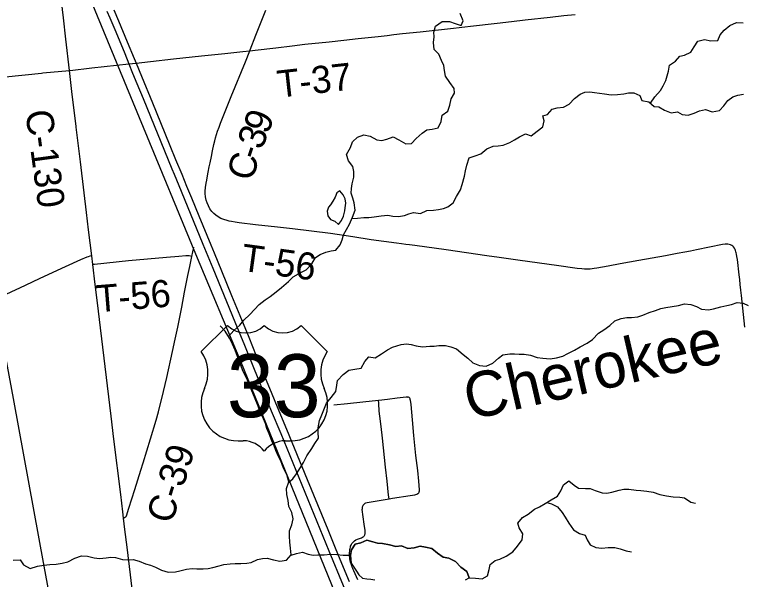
# Model space of a CAD drawing. Extents: x 0 to 34, y -5.4 to 22.
# Drawn here: x 6.179 to 7.705, y 15.309 to 16.492 of the extents above; entities that cross this region are included whole.
import ezdxf

# ---------------------------------------------------------------- set-up
doc = ezdxf.new("R2010")
doc.units = 0
for name, color, linetype in [('GM_X_County_Road', 7, 'Continuous'), ('GM_X_County_Road_Text', 7, 'Continuous'), ('GM_X_Minor_Lake', 7, 'Continuous'), ('GM_X_Minor_River', 7, 'Continuous'), ('GM_X_Minor_River_Text', 7, 'Continuous'), ('GM_X_Rail_Line', 7, 'Continuous'), ('GM_X_Township_Road', 7, 'Continuous'), ('GM_X_Township_Road_Text', 7, 'Continuous'), ('GM_X_US_Location', 7, 'Continuous'), ('GM_X_US_Route', 7, 'Continuous'), ('GM_X_US_Shield', 7, 'Continuous')]:
    doc.layers.add(name, color=color, linetype=linetype)

msp = doc.modelspace()

# ---------------------------------------------------------------- linework, layer by layer
at = {"layer": 'GM_X_County_Road'}
msp.add_line((6.3428, 15.9686), (6.3405, 15.9872), dxfattribs=at)
for points in [[(6.2815, 16.4857), (6.2776, 16.5205), (6.2729, 16.5674)], [(6.5919, 16.0798), (6.588, 16.0855), (6.5847, 16.0918), (6.5821, 16.0978), (6.58, 16.1037), (6.5787, 16.1105), (6.5782, 16.1172), (6.5783, 16.1221), (6.5788, 16.1301), (6.5801, 16.1392), (6.5813, 16.1453), (6.583, 16.1542), (6.5845, 16.1618), (6.5867, 16.173), (6.5884, 16.1816), (6.5912, 16.1953), (6.5935, 16.2065), (6.5964, 16.2202), (6.5982, 16.2276), (6.5999, 16.234), (6.6018, 16.2408), (6.604, 16.2477), (6.6072, 16.2564), (6.6101, 16.2646), (6.6183, 16.2854), (6.6327, 16.3204), (6.6622, 16.393), (6.6714, 16.4165), (6.6722, 16.4184), (6.6843, 16.4492), (6.6965, 16.4804), (6.7049, 16.5017)], [(6.3081, 16.2562), (6.3079, 16.2582), (6.2995, 16.3248), (6.2938, 16.3751), (6.2864, 16.4409), (6.2815, 16.4857)], [(6.4185, 16.3889), (6.4334, 16.3904), (6.4635, 16.3939), (6.5117, 16.3995), (6.5704, 16.4057), (6.6193, 16.4107), (6.657, 16.4148), (6.6714, 16.4165)], [(6.2351, 16.3696), (6.2381, 16.3699), (6.2938, 16.3751), (6.2957, 16.3753), (6.3407, 16.3804), (6.4185, 16.3889)], [(4.7185, 16.204), (4.7926, 16.2124), (4.8952, 16.2234), (5.0348, 16.2385), (5.0448, 16.2396), (5.088, 16.2444), (5.2441, 16.2625), (5.3244, 16.2711), (5.3683, 16.2761), (5.4411, 16.2844), (5.561, 16.2977), (5.6252, 16.3051), (5.6696, 16.3102), (5.688, 16.3123), (5.7221, 16.3161), (5.769, 16.3213), (5.8104, 16.3259), (5.8666, 16.332), (5.9123, 16.337), (6.0063, 16.3464), (6.1102, 16.3568), (6.1602, 16.3621), (6.2351, 16.3696)], [(6.3405, 15.9872), (6.3339, 16.0417), (6.3298, 16.0775), (6.3248, 16.1188), (6.3169, 16.1836), (6.3081, 16.2562)], [(6.4073, 15.4374), (6.4092, 15.4386), (6.4111, 15.44), (6.4125, 15.4412), (6.4132, 15.4423), (6.4186, 15.4584), (6.4309, 15.4975), (6.4434, 15.5378), (6.4482, 15.5532), (6.4637, 15.6037), (6.4753, 15.6424), (6.4802, 15.6603), (6.4907, 15.7025), (6.4978, 15.7321), (6.5098, 15.7867), (6.5151, 15.8122), (6.5205, 15.8378), (6.529, 15.8791), (6.5351, 15.9108), (6.5421, 15.9455), (6.5462, 15.9644), (6.5504, 15.9858), (6.5543, 16.0054)], [(6.4464, 15.1211), (6.4431, 15.144), (6.4342, 15.2168), (6.4265, 15.2778), (6.4217, 15.3185), (6.4147, 15.3765), (6.4102, 15.4135), (6.4073, 15.4374), (6.4056, 15.4505), (6.4013, 15.4867), (6.3872, 15.6026), (6.3811, 15.6513), (6.3588, 15.8364), (6.3525, 15.8882), (6.3478, 15.927), (6.3428, 15.9686)]]:
    msp.add_lwpolyline(points, dxfattribs=at)
at = {"layer": 'GM_X_Minor_Lake'}
for points in [[(6.8701, 16.0814), (6.8713, 16.0877), (6.8722, 16.0972), (6.8712, 16.1063), (6.8672, 16.1144), (6.8601, 16.1228), (6.854, 16.1188), (6.8505, 16.1097), (6.845, 16.1014), (6.8404, 16.0935)], [(6.8404, 16.0935), (6.8361, 16.0887), (6.8333, 16.0803), (6.8351, 16.0708), (6.8407, 16.0628), (6.8493, 16.0592), (6.8575, 16.0522), (6.8637, 16.0609), (6.8677, 16.0699), (6.8701, 16.0814)], [(7.1305, 15.3128), (7.1261, 15.3254), (7.1134, 15.3347), (7.1023, 15.3466), (7.088, 15.3537), (7.0763, 15.3558), (7.0647, 15.3643), (7.0528, 15.3736), (7.0396, 15.3765), (7.0279, 15.3786), (7.0157, 15.3754), (7.0021, 15.3737), (6.9893, 15.3793), (6.9772, 15.378), (6.9636, 15.3816), (6.9492, 15.3841), (6.9387, 15.3851), (6.9289, 15.3879), (6.9164, 15.3915), (6.9039, 15.386), (6.8917, 15.3832), (6.8847, 15.3712), (6.8823, 15.3598)], [(6.8823, 15.3598), (6.8829, 15.3514), (6.884, 15.343), (6.8891, 15.335), (6.8951, 15.3262), (6.8995, 15.3185), (6.9077, 15.3119), (6.9168, 15.3102), (6.9247, 15.3094), (6.9331, 15.3081)], [(7.1233, 15.3085), (7.1305, 15.3128)]]:
    msp.add_lwpolyline(points, dxfattribs=at)
at = {"layer": 'GM_X_Minor_River'}
for points in [[(6.627, 15.8176), (6.638, 15.8302), (6.6503, 15.8414), (6.6592, 15.8519), (6.6715, 15.8638), (6.6815, 15.8746), (6.6912, 15.8847), (6.7038, 15.8947), (6.7138, 15.9018), (6.7268, 15.9114), (6.7379, 15.9203), (6.7525, 15.933), (6.7625, 15.9427), (6.7786, 15.9519), (6.7896, 15.9574), (6.8016, 15.9701), (6.809, 15.9836), (6.8185, 15.9895), (6.8304, 15.9946), (6.8421, 15.9971), (6.8516, 15.9988), (6.8609, 16.0097), (6.8645, 16.0206), (6.8677, 16.0308), (6.8739, 16.0421), (6.8801, 16.053), (6.8868, 16.068), (6.892, 16.0824), (6.89, 16.0976), (6.8875, 16.1075), (6.8839, 16.1182), (6.8844, 16.1277), (6.8861, 16.1379), (6.8894, 16.1519), (6.8892, 16.1632), (6.8871, 16.1739), (6.8782, 16.1862), (6.8742, 16.1988), (6.8824, 16.2135), (6.8864, 16.2259), (6.8968, 16.2352), (6.9101, 16.2403), (6.9237, 16.2374), (6.9376, 16.23), (6.9478, 16.2287), (6.958, 16.2315), (6.9714, 16.2362), (6.9837, 16.2296), (6.998, 16.2217), (7.0101, 16.2223), (7.0197, 16.2324), (7.032, 16.2435), (7.0424, 16.2506), (7.053, 16.2523), (7.0659, 16.2551), (7.0722, 16.2683), (7.0743, 16.2815), (7.0861, 16.2897), (7.0901, 16.3025), (7.093, 16.3157), (7.1, 16.3278), (7.0994, 16.3373), (7.0902, 16.3499), (7.0809, 16.363), (7.0788, 16.3752), (7.0775, 16.3858), (7.0728, 16.3962), (7.0673, 16.4095), (7.0576, 16.4192), (7.0563, 16.4336), (7.0577, 16.4457), (7.0567, 16.4552), (7.0599, 16.4677), (7.0741, 16.4777), (7.0892, 16.4778), (7.1013, 16.4735), (7.1141, 16.4694), (7.1184, 16.4792), (7.1115, 16.4942)], [(7.5101, 16.3066), (7.5196, 16.3202), (7.5312, 16.3333), (7.5366, 16.3431), (7.5421, 16.3544), (7.5453, 16.3642), (7.5477, 16.374), (7.5502, 16.3861), (7.5624, 16.3946), (7.5717, 16.4051), (7.5816, 16.4072), (7.5949, 16.4134), (7.6015, 16.4247), (7.6093, 16.4363), (7.623, 16.4403), (7.6366, 16.437), (7.6513, 16.4379), (7.6564, 16.4499), (7.6645, 16.4597), (7.6764, 16.469), (7.6905, 16.4759), (7.7045, 16.4749)], [(6.8855, 16.065), (6.897, 16.066), (6.9103, 16.0669), (6.9205, 16.0675), (6.9319, 16.0688), (6.9467, 16.0704), (6.9603, 16.0721), (6.9709, 16.0697), (6.9826, 16.0691), (6.9951, 16.0711), (7.0046, 16.0751), (7.0145, 16.078), (7.0289, 16.0759), (7.0422, 16.0821), (7.0562, 16.0826), (7.0668, 16.0836), (7.0767, 16.0857), (7.0862, 16.0897), (7.0974, 16.0982), (7.1044, 16.111), (7.1126, 16.1253), (7.1158, 16.1362), (7.1206, 16.1536), (7.1227, 16.165), (7.1255, 16.1771), (7.1307, 16.1921), (7.1433, 16.1965), (7.1551, 16.2005), (7.1677, 16.2112), (7.1807, 16.2167), (7.1913, 16.2173), (7.2019, 16.2186), (7.2156, 16.2245), (7.2256, 16.23), (7.2359, 16.2359), (7.2488, 16.2421), (7.2605, 16.2381), (7.2728, 16.2478), (7.285, 16.2571), (7.2875, 16.2699), (7.2847, 16.2798), (7.2946, 16.2827), (7.3042, 16.2943), (7.3148, 16.2971), (7.3285, 16.2984), (7.3399, 16.3043), (7.3511, 16.3166), (7.363, 16.3255), (7.3725, 16.3299), (7.3835, 16.3305), (7.3933, 16.3288), (7.4137, 16.3262), (7.4277, 16.3241), (7.4413, 16.3246), (7.4542, 16.3259), (7.4645, 16.3284), (7.4754, 16.3282), (7.4882, 16.3226), (7.4922, 16.3123), (7.5065, 16.3098), (7.5181, 16.2994), (7.5279, 16.2988), (7.5399, 16.2922), (7.5535, 16.2866), (7.5667, 16.2883), (7.5765, 16.2832), (7.589, 16.2815), (7.6019, 16.2854), (7.6126, 16.2905), (7.6255, 16.2934), (7.6394, 16.2886), (7.655, 16.291), (7.6638, 16.301), (7.672, 16.3119), (7.6827, 16.3201), (7.693, 16.3237), (7.7051, 16.3258)], [(6.7526, 15.5119), (6.7615, 15.5197), (6.7693, 15.5306), (6.7774, 15.5433), (6.7837, 15.5542), (6.7911, 15.5681), (6.8012, 15.5831), (6.8078, 15.594), (6.8152, 15.6049), (6.8146, 15.6167), (6.8144, 15.6265), (6.8177, 15.642), (6.8221, 15.6541), (6.8264, 15.6643), (6.8319, 15.6782), (6.8416, 15.6902), (6.8516, 15.7029), (6.8534, 15.7162), (6.855, 15.726), (6.867, 15.7387), (6.8789, 15.7472), (6.8914, 15.7497), (6.9047, 15.7517), (6.9125, 15.7656), (6.921, 15.7757), (6.9342, 15.7736), (6.9475, 15.7813), (6.9594, 15.7902), (6.9701, 15.7957), (6.9884, 15.8011), (6.9994, 15.8025), (7.0092, 15.8011), (7.0197, 15.7987), (7.0329, 15.7966), (7.0481, 15.7974), (7.0576, 15.798), (7.0671, 15.7994), (7.081, 15.7988), (7.092, 15.7963), (7.104, 15.7919), (7.1182, 15.7803), (7.1279, 15.7726), (7.1387, 15.7625), (7.1523, 15.7574), (7.1666, 15.756), (7.18, 15.7622), (7.1919, 15.7726), (7.2015, 15.7797), (7.2155, 15.7817), (7.2253, 15.7819), (7.2352, 15.7806), (7.2461, 15.7812), (7.259, 15.7787), (7.2733, 15.7743), (7.285, 15.7729), (7.3005, 15.7711), (7.3138, 15.7736), (7.3267, 15.7771), (7.337, 15.7826), (7.3515, 15.7892), (7.3629, 15.7962), (7.3775, 15.804), (7.3886, 15.8117), (7.4013, 15.8252), (7.4127, 15.8322), (7.4254, 15.8411), (7.4358, 15.8511), (7.4491, 15.8558), (7.4605, 15.8575), (7.4703, 15.8574), (7.4836, 15.8591), (7.4942, 15.8623), (7.5076, 15.8681), (7.5205, 15.8721), (7.5316, 15.8764), (7.5422, 15.8789), (7.5558, 15.881), (7.5691, 15.883), (7.5817, 15.8862), (7.5945, 15.8848), (7.6066, 15.8805), (7.6171, 15.8754), (7.6318, 15.8736), (7.642, 15.8757), (7.6576, 15.88), (7.6702, 15.8832), (7.6801, 15.8853), (7.6918, 15.8889), (7.7043, 15.8879), (7.7148, 15.8832)], [(6.2905, 15.3463), (6.305, 15.3537), (6.3191, 15.3584), (6.332, 15.3582), (6.3455, 15.3541), (6.3569, 15.3532), (6.3709, 15.3541), (6.3804, 15.3558), (6.3902, 15.3553), (6.4053, 15.3512), (6.4151, 15.3503), (6.4272, 15.3509), (6.4396, 15.3473), (6.4528, 15.3417), (6.4637, 15.3393), (6.4742, 15.3345), (6.4866, 15.3286), (6.5009, 15.3246), (6.5157, 15.3251), (6.5252, 15.3268), (6.5389, 15.3304), (6.5506, 15.3317), (6.5605, 15.3312), (6.5737, 15.331), (6.584, 15.3323), (6.5942, 15.3344), (6.6075, 15.3376), (6.6174, 15.3401), (6.6303, 15.3418), (6.6409, 15.3427), (6.653, 15.3425), (6.6651, 15.3431), (6.6746, 15.3448), (6.6876, 15.3506), (6.6982, 15.3531), (6.7081, 15.3537), (6.7212, 15.3501), (6.7344, 15.3472), (6.7481, 15.3496), (6.7581, 15.3604), (6.7565, 15.3745), (6.7555, 15.3874), (6.7546, 15.4), (6.7544, 15.4106), (6.7592, 15.4238), (6.7624, 15.4359), (6.7596, 15.4492), (6.753, 15.4618), (6.7521, 15.4747), (6.7489, 15.4869), (6.7483, 15.4994), (6.7531, 15.5134), (6.7488, 15.5286), (6.7422, 15.5424), (6.7364, 15.5577), (6.7306, 15.568), (6.7262, 15.5791), (6.7222, 15.5887), (6.7175, 15.5997), (6.712, 15.6139), (6.7069, 15.6253), (6.7041, 15.6356), (6.7001, 15.6452), (6.6935, 15.6601), (6.6888, 15.6723), (6.683, 15.6872), (6.6775, 15.699), (6.6724, 15.7128), (6.667, 15.7262), (6.6611, 15.738), (6.6564, 15.7483), (6.6513, 15.7617), (6.6455, 15.7762), (6.6408, 15.7892), (6.6353, 15.8022), (6.6291, 15.8144), (6.6199, 15.829), (6.6094, 15.8402)], [(6.7578, 15.3602), (6.7695, 15.3633), (6.7821, 15.3665), (6.7937, 15.3617), (6.8043, 15.3597), (6.8137, 15.3603), (6.827, 15.3604), (6.8406, 15.3621), (6.8535, 15.3615), (6.8667, 15.3601), (6.8823, 15.3598), (6.8847, 15.3712), (6.8917, 15.3832), (6.9039, 15.386), (6.9164, 15.3915), (6.9289, 15.3879), (6.9387, 15.3851), (6.9492, 15.3841), (6.9636, 15.3816), (6.9772, 15.378), (6.9893, 15.3793), (7.0021, 15.3737), (7.0157, 15.3754), (7.0279, 15.3786), (7.0396, 15.3765), (7.0528, 15.3736), (7.0647, 15.3643), (7.0763, 15.3558), (7.088, 15.3537), (7.1023, 15.3466), (7.1134, 15.3347), (7.1261, 15.3254), (7.1305, 15.3128), (7.1441, 15.3118), (7.158, 15.3104), (7.1688, 15.317), (7.1724, 15.3299), (7.1744, 15.3401), (7.1848, 15.349), (7.1951, 15.3515), (7.2084, 15.3577), (7.2218, 15.367), (7.2322, 15.3785), (7.2419, 15.392), (7.2433, 15.4049), (7.2351, 15.4172), (7.2323, 15.4271), (7.2423, 15.4391), (7.2542, 15.4457), (7.2676, 15.4561), (7.2779, 15.4612), (7.2901, 15.4682), (7.302, 15.4756), (7.3154, 15.4837), (7.3224, 15.495), (7.3282, 15.5074), (7.339, 15.5156), (7.3502, 15.5063), (7.3599, 15.5004), (7.3739, 15.4998), (7.3837, 15.4996), (7.3946, 15.4956), (7.4089, 15.4905), (7.4191, 15.4899), (7.4294, 15.492), (7.4446, 15.4963), (7.4545, 15.4984), (7.4647, 15.4982), (7.4802, 15.4964), (7.49, 15.4951), (7.5025, 15.4938), (7.5157, 15.4917), (7.5296, 15.4873), (7.5439, 15.484), (7.5579, 15.4818), (7.5715, 15.4812), (7.5817, 15.4803), (7.5944, 15.471), (7.6042, 15.4689)], [(7.2931, 15.4701), (7.3033, 15.4672), (7.3157, 15.4613), (7.3254, 15.4494), (7.3316, 15.4394), (7.3394, 15.4272), (7.3494, 15.4133), (7.3617, 15.4055), (7.3734, 15.4015), (7.3778, 15.392), (7.384, 15.3816), (7.3961, 15.3761), (7.4085, 15.3748), (7.4214, 15.3757), (7.4354, 15.3758), (7.4471, 15.373), (7.4595, 15.3693), (7.4708, 15.3669)], [(6.1763, 15.3498), (6.1907, 15.3499), (6.1981, 15.3399), (6.2116, 15.3321), (6.2272, 15.3372), (6.2401, 15.3392), (6.253, 15.3402), (6.2662, 15.3414), (6.2787, 15.3431), (6.2905, 15.3463)]]:
    msp.add_lwpolyline(points, dxfattribs=at)
at = {"layer": 'GM_X_Rail_Line'}
for points in [[(6.1298, 17.0307), (6.0905, 16.9105), (6.0657, 16.8233), (6.0521, 16.7659), (6.0427, 16.7106), (6.0374, 16.6619), (6.0337, 16.61), (6.035, 16.5368), (6.0346, 16.4766), (6.0418, 16.428), (6.0526, 16.3516), (6.0987, 16.1024), (6.1764, 15.688), (6.2405, 15.3368), (6.3349, 14.8243), (6.4523, 14.2374), (6.4858, 14.1034), (6.4871, 14.1)], [(6.1298, 17.0307), (6.1657, 16.9396), (6.2331, 16.7878), (6.3387, 16.522), (6.5579, 15.9912), (6.6517, 15.7661), (6.8965, 15.1669), (7.1452, 14.5708), (7.2659, 14.2765), (7.3176, 14.1508), (7.3404, 14.1)]]:
    msp.add_lwpolyline(points, dxfattribs=at)
at = {"layer": 'GM_X_Township_Road'}
msp.add_line((6.3428, 15.9686), (6.3405, 15.9872), dxfattribs=at)
for points in [[(6.6714, 16.4165), (6.6826, 16.4179), (6.7257, 16.4229), (6.7604, 16.4269), (6.7869, 16.4301), (6.8375, 16.4354), (6.8684, 16.4387), (6.8981, 16.4418), (6.9401, 16.4464), (6.9591, 16.4486), (6.9728, 16.4502), (6.9913, 16.4523), (7.0284, 16.4563), (7.0976, 16.4637), (7.1333, 16.4678), (7.1895, 16.4744), (7.2191, 16.4778), (7.2482, 16.4809), (7.3, 16.4867), (7.329, 16.49), (7.3525, 16.4927)], [(6.7293, 16.0468), (6.6834, 16.0521), (6.6489, 16.0563), (6.6406, 16.0574), (6.633, 16.0587), (6.6285, 16.0595), (6.6239, 16.0607), (6.6169, 16.0628), (6.6107, 16.0654), (6.6053, 16.0683), (6.6003, 16.0718), (6.5961, 16.0754), (6.5919, 16.0798)], [(7.1937, 15.9835), (7.1679, 15.9872), (7.0823, 15.9993), (7.0169, 16.0082), (7.006, 16.0096), (6.9982, 16.0108), (6.989, 16.0121), (6.9789, 16.0132), (6.9257, 16.0207), (6.8873, 16.0264), (6.8407, 16.0335), (6.7612, 16.0432), (6.7293, 16.0468)], [(7.7075, 15.8375), (7.7021, 15.8906), (7.7008, 15.9041), (7.6997, 15.9148), (7.6983, 15.9269), (7.697, 15.9376), (7.6959, 15.9472), (7.6922, 15.9795), (7.6913, 15.9858), (7.6905, 15.9907), (7.6898, 15.9934), (7.6892, 15.9956), (7.6885, 15.9978), (7.6875, 16.0002), (7.6858, 16.0031), (7.6839, 16.0055), (7.6824, 16.0071), (7.6805, 16.0085), (7.6778, 16.0099), (7.6751, 16.0109), (7.6721, 16.0114), (7.6695, 16.0116), (7.6669, 16.0113), (7.6607, 16.0103), (7.6066, 15.9992), (7.5938, 15.9967), (7.5824, 15.9945), (7.5663, 15.9915), (7.5419, 15.9871), (7.4855, 15.9771), (7.4466, 15.9701), (7.4219, 15.9655), (7.3977, 15.961), (7.3924, 15.9601), (7.3879, 15.9595), (7.3838, 15.9591), (7.3793, 15.9589), (7.3757, 15.9589), (7.3719, 15.959), (7.3664, 15.9594), (7.3571, 15.9603), (7.3138, 15.9664), (7.2372, 15.9774), (7.1937, 15.9835)], [(6.3405, 15.9872), (6.3369, 15.9861), (6.3334, 15.9851), (6.3303, 15.984), (6.3174, 15.9786), (6.2849, 15.9637), (6.2322, 15.9394), (6.2013, 15.9249), (6.1605, 15.9061), (6.1452, 15.8989)], [(6.5504, 15.9858), (6.5473, 15.9864), (6.5446, 15.9869), (6.5412, 15.9872), (6.5374, 15.9871), (6.5227, 15.9857), (6.4973, 15.9836), (6.4175, 15.9764), (6.3461, 15.9689), (6.3428, 15.9686)], [(6.8471, 15.6747), (6.876, 15.6778), (6.9083, 15.6812), (6.9408, 15.6845), (6.9419, 15.6846), (6.9597, 15.687), (6.9799, 15.6894), (6.9988, 15.6913), (7.001, 15.6914), (7.0026, 15.6911)], [(6.9629, 15.478), (6.9621, 15.4858), (6.9588, 15.5149), (6.9556, 15.5445), (6.9491, 15.6053), (6.9462, 15.6292), (6.9438, 15.6511), (6.9426, 15.6619), (6.9422, 15.6671), (6.9418, 15.672), (6.9413, 15.678), (6.9408, 15.6845)], [(7.0231, 15.4888), (7.0244, 15.49), (7.025, 15.4908), (7.0257, 15.492), (7.0263, 15.4931), (7.0267, 15.4942), (7.0268, 15.4952), (7.0269, 15.4969), (7.0252, 15.5146), (7.0229, 15.5374), (7.019, 15.5688), (7.015, 15.6104), (7.012, 15.6436), (7.0091, 15.6758), (7.0085, 15.6806), (7.0078, 15.6842), (7.0074, 15.686), (7.0069, 15.6877), (7.0062, 15.689), (7.0053, 15.6899), (7.004, 15.6906), (7.0026, 15.6911)], [(6.9629, 15.478), (6.9703, 15.4792), (7.0071, 15.4851), (7.0169, 15.4866), (7.0191, 15.487), (7.0209, 15.4877), (7.0231, 15.4888)], [(6.913, 15.406), (6.9132, 15.4079), (6.9132, 15.4091), (6.9132, 15.4103), (6.913, 15.4117), (6.9112, 15.4252), (6.907, 15.4554), (6.9071, 15.4577), (6.9073, 15.4594), (6.9077, 15.4613), (6.9082, 15.4628), (6.9091, 15.4645), (6.9101, 15.4658), (6.9115, 15.4675), (6.9128, 15.4686), (6.9146, 15.4696), (6.9169, 15.4701), (6.9379, 15.4738), (6.9629, 15.478)], [(6.8979, 15.3082), (6.8892, 15.3271), (6.8881, 15.3299), (6.8871, 15.3322), (6.886, 15.3349), (6.885, 15.3376), (6.8835, 15.3419), (6.8826, 15.3453), (6.8817, 15.3488), (6.8811, 15.3521), (6.8807, 15.3553), (6.8805, 15.3577), (6.8803, 15.3617), (6.8804, 15.3647), (6.8806, 15.3687), (6.881, 15.3716), (6.8814, 15.3741), (6.882, 15.3766), (6.8826, 15.3785), (6.8835, 15.3808), (6.8844, 15.3827), (6.8853, 15.3842), (6.8864, 15.3858), (6.8876, 15.3873), (6.889, 15.3887), (6.8905, 15.39), (6.8937, 15.3921), (6.8968, 15.3934), (6.901, 15.3949), (6.905, 15.3965), (6.9076, 15.3977), (6.909, 15.3983), (6.91, 15.3991), (6.9109, 15.4001), (6.9117, 15.4012), (6.9121, 15.4022), (6.9124, 15.403), (6.9127, 15.4046), (6.913, 15.406)]]:
    msp.add_lwpolyline(points, dxfattribs=at)
at = {"layer": 'GM_X_US_Route'}
for points in [[(6.3725, 16.4994), (6.3786, 16.4855), (6.3909, 16.4564), (6.4098, 16.4106), (6.4185, 16.3889), (6.4262, 16.3695), (6.435, 16.3476), (6.448, 16.3164), (6.5085, 16.1692), (6.513, 16.1582)], [(6.3872, 16.5019), (6.3969, 16.4792), (6.4148, 16.4354), (6.4293, 16.4002), (6.4334, 16.3904), (6.4447, 16.3631), (6.4675, 16.3071), (6.4842, 16.2664), (6.5042, 16.2177), (6.5162, 16.1885), (6.5289, 16.1578), (6.539, 16.1331), (6.5491, 16.1084), (6.5648, 16.0706), (6.5814, 16.0303), (6.5899, 16.0096), (6.5968, 15.9929), (6.6123, 15.9552), (6.6335, 15.9038), (6.6506, 15.8618), (6.6692, 15.8164), (6.6851, 15.7776), (6.7059, 15.7267), (6.7177, 15.6979), (6.7288, 15.6709), (6.7482, 15.6239), (6.7917, 15.5181), (6.8346, 15.4137), (6.8503, 15.3756), (6.8635, 15.3433), (6.8794, 15.3046)], [(6.513, 16.1582), (6.5275, 16.1223), (6.5729, 16.0113), (6.5938, 15.9611), (6.6401, 15.8489), (6.6602, 15.7999), (6.6913, 15.724), (6.7164, 15.6624), (6.7363, 15.6145), (6.8369, 15.3693), (6.8669, 15.2965), (6.9119, 15.1873), (6.9188, 15.1706)]]:
    msp.add_lwpolyline(points, dxfattribs=at)
at = {"layer": 'GM_X_US_Shield'}
for p, q in [((6.625, 15.8412), (6.57, 15.7863)), ((6.8337, 15.7863), (6.7788, 15.8412)), ((6.6469, 15.5995), (6.6579, 15.5995)), ((6.7458, 15.5995), (6.7568, 15.5995))]:
    msp.add_line(p, q, dxfattribs=at)
for centre, radius, start, end in [((6.6634, 15.8804), 0.0549, 225.573, 314.427), ((6.7403, 15.8804), 0.0549, 225.573, 314.427), ((6.507, 15.7421), 0.0769, 334.5471, 35.0009), ((6.8967, 15.7421), 0.0769, 144.9991, 205.4529), ((6.6461, 15.6764), 0.0769, 154.8319, 270.6383), ((6.7576, 15.6764), 0.0769, 269.3617, 25.1681), ((6.6579, 15.5446), 0.0549, 36.8699, 90), ((6.7458, 15.5446), 0.0549, 90, 143.1301)]:
    msp.add_arc(centre, radius, start, end, dxfattribs=at)

# ---------------------------------------------------------------- texts
at = {"layer": 'GM_X_County_Road_Text'}
for s, height, rotation, p in [('C-130', 0.05682, 277.7028, (6.2014, 16.2894)), ('9', 0.0568, 68.5126, (6.7089, 16.2396)), ('3', 0.0568, 69.7595, (6.6969, 16.2071)), ('-', 0.0568, 71.3774, (6.6896, 16.1854)), ('C', 0.0568, 74.3135, (6.6772, 16.1412)), ('C-39', 0.05682, 72.6418, (6.5081, 15.4234))]:
    msp.add_text(s, height=height, rotation=rotation, dxfattribs=at).set_placement(p)
at = {"layer": 'GM_X_Minor_River_Text'}
msp.add_text('Cherokee', height=0.0947, rotation=13.0236, dxfattribs=at).set_placement((7.1319, 15.6422))
at = {"layer": 'GM_X_Township_Road_Text'}
for s, rotation, p in [('T-37', 6.3797, (6.732, 16.318)), ('T-56', 352.2052, (6.6511, 15.9561)), ('T-56', 4.5881, (6.3522, 15.8685))]:
    msp.add_text(s, height=0.05682, rotation=rotation, dxfattribs=at).set_placement(p)
at = {"layer": 'GM_X_US_Location'}
for s in ['0', '/']:
    msp.add_text(s, height=0.000189, dxfattribs=at).set_placement((6.7018, 15.7138))
msp.add_text('33', height=0.000189, rotation=0, dxfattribs=at).set_placement((6.6627, 15.6746))
at = {"layer": 'GM_X_US_Shield'}
msp.add_text('33', height=0.13184, dxfattribs=at).set_placement((6.6236, 15.6489))

doc.saveas('drawing.dxf')
